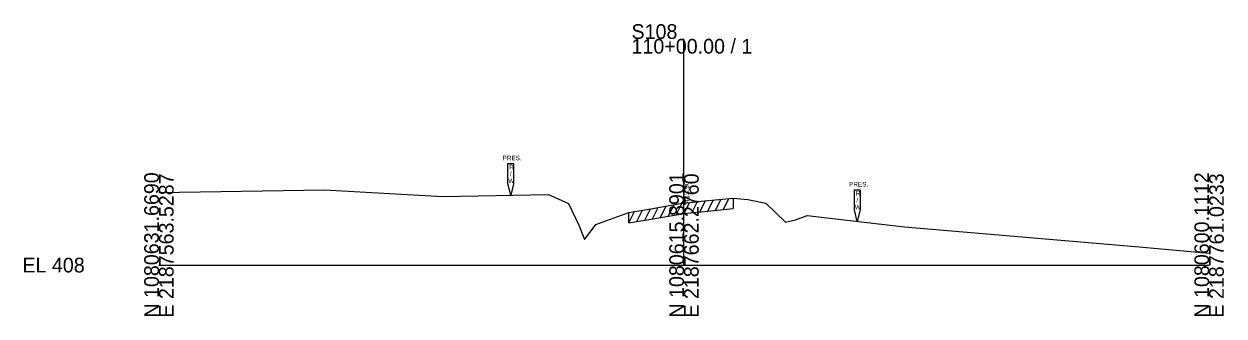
# Model space of a CAD drawing. Extents: x -26 to 2203, y 490 to 19581.
# Drawn here: x -25.7 to 202.8, y 13490.3 to 13545.9 of the extents above; entities that cross this region are included whole.
import ezdxf

# ---------------------------------------------------------------- set-up
doc = ezdxf.new("R2010")
doc.units = 0
for name, color, linetype in [('RD_GPK_XS_Cell', 7, 'Continuous'), ('RD_XS_ExGround', 7, 'Continuous'), ('RD_XS_ExPaveRet', 7, 'Continuous'), ('RD_XS_ExRW', 7, 'Continuous'), ('RD_XS_TX_Elev_EX', 7, 'Continuous')]:
    doc.layers.add(name, color=color, linetype=linetype)

msp = doc.modelspace()

# ---------------------------------------------------------------- linework, layer by layer
at = {"layer": 'RD_GPK_XS_Cell'}
for p, q in [((100, 13500), (100, 13543.11)), ((0, 13500), (100, 13500)), ((100, 13500), (200, 13500))]:
    msp.add_line(p, q, dxfattribs=at)
at = {"layer": 'RD_XS_ExGround'}
msp.add_lwpolyline([(0, 13513.85), (31.54, 13514.37), (54.07, 13513.1), (74.18, 13513.47), (77.98, 13511.75), (79.98, 13507.63), (81.06, 13504.86), (82.33, 13506.54), (83.23, 13507.76), (86.69, 13509), (89.51, 13510.06), (93.66, 13510.76), (99.33, 13511.73), (100, 13511.81), (103.88, 13512.25), (109.39, 13512.77), (112.18, 13512.48), (115.6, 13511.84), (117.5, 13509.98), (119.31, 13508.21), (121.22, 13508.65), (123.45, 13509.46), (134.9, 13508.11), (141.98, 13507.28), (186.69, 13503.52), (200, 13502.3)], dxfattribs=at)
at = {"layer": 'RD_XS_ExPaveRet'}
for p, q in [((94.01, 13508.82), (95.1, 13511.01)), ((95.51, 13509.08), (96.6, 13511.27)), ((97.01, 13509.34), (98.1, 13511.52)), ((98.51, 13509.59), (99.6, 13511.76)), ((100.01, 13509.81), (101.07, 13511.93)), ((101.51, 13509.98), (102.57, 13512.1)), ((103.01, 13510.15), (104.07, 13512.26)), ((104.51, 13510.31), (105.56, 13512.41)), ((106.01, 13510.45), (107.06, 13512.55)), ((107.51, 13510.59), (108.56, 13512.69)), ((109.39, 13512.77), (109.39, 13510.77)), ((89.51, 13508.06), (90.6, 13510.24)), ((89.51, 13508.06), (89.51, 13510.06)), ((89.51, 13508.06), (93.66, 13508.76)), ((91.01, 13508.31), (92.1, 13510.5)), ((92.51, 13508.57), (93.6, 13510.75)), ((93.66, 13508.76), (99.33, 13509.73)), ((99.33, 13509.73), (100, 13509.81)), ((100, 13509.81), (103.88, 13510.25)), ((103.88, 13510.25), (109.39, 13510.77))]:
    msp.add_line(p, q, dxfattribs=at)
at = {"layer": 'RD_XS_ExRW'}
for points in [[(66.45, 13519.35), (67.55, 13519.35), (67.55, 13515.52), (67, 13513.34), (66.45, 13515.52)], [(132.45, 13514.35), (133.55, 13514.35), (133.55, 13510.52), (133, 13508.34), (132.45, 13510.52)]]:
    msp.add_lwpolyline(points, close=True, dxfattribs=at)

# ---------------------------------------------------------------- texts
at = {"layer": 'RD_GPK_XS_Cell'}
for s, p in [('S108', (90, 13543.11)), ('110+00.00 / 1', (90, 13540.31)), ('EL 408', (-26, 13498.6))]:
    msp.add_text(s, height=2.8, dxfattribs=at).set_placement(p)
for s, p in [('N 1080631.6690', (0, 13490)), ('E 2187563.5287', (2.8, 13490)), ('N 1080615.8901', (100, 13490)), ('E 2187662.2760', (102.8, 13490)), ('N 1080600.1112', (200, 13490)), ('E 2187761.0233', (202.8, 13490))]:
    msp.add_text(s, height=2.8, rotation=90, dxfattribs=at).set_placement(p)
at = {"layer": 'RD_XS_ExRW'}
for s, p in [('PRES.', (65.45, 13519.98)), ('R', (66.71, 13518.26)), ('/', (66.83, 13516.95)), ('W', (66.53, 13515.63)), ('PRES.', (131.45, 13514.98)), ('R', (132.71, 13513.26)), ('W', (132.53, 13510.64)), ('/', (132.83, 13511.95))]:
    msp.add_text(s, height=0.875, dxfattribs=at).set_placement(p)
at = {"layer": 'RD_XS_TX_Elev_EX'}
msp.add_text('413.90', height=1, rotation=90, dxfattribs=at).set_placement((101, 13511.81))

doc.saveas('drawing.dxf')
